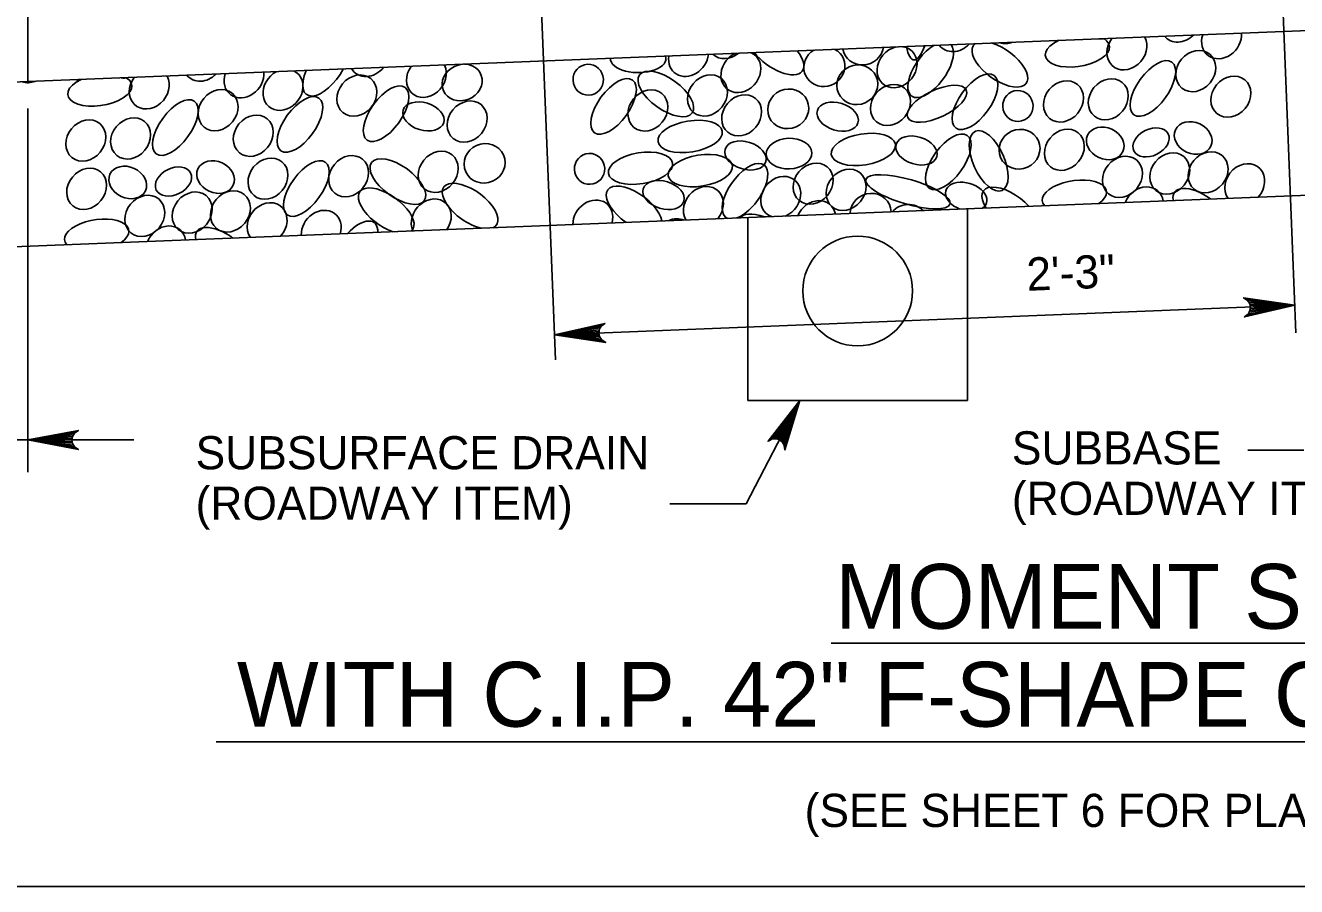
# Model space of a CAD drawing. Extents: x 638167 to 640248, y 296544 to 298920.
# Drawn here: x 638288.4 to 638406.1, y 297747.5 to 297827.2 of the extents above; entities that cross this region are included whole.
import ezdxf

# ---------------------------------------------------------------- set-up
doc = ezdxf.new("R2010")
doc.units = 0
doc.layers.add('1', color=7, linetype='Continuous')

msp = doc.modelspace()

# ---------------------------------------------------------------- linework, layer by layer
at = {"layer": '1'}
for p, q in [((638288.65, 297857.77), (638288.65, 297822.04)), ((638288.65, 297822.04), (638633.99, 297835.85)), ((638404.73, 297832.07), (638406.06, 297798.78)), ((638336.23, 297828.65), (638337.52, 297796.27)), ((638273.64, 297821.44), (638288.65, 297822.04)), ((638274.25, 297806.21), (638634.6, 297820.62)), ((638288.65, 297785.85), (638288.65, 297819.54)), ((638375.65, 297810.27), (638375.65, 297792.49)), ((638355.32, 297809.45), (638355.32, 297792.49)), ((638337.43, 297798.58), (638405.96, 297801.32)), ((638355.16, 297782.92), (638360.15, 297792.49)), ((638355.32, 297792.49), (638375.65, 297792.49)), ((638263.78, 297788.85), (638298.47, 297788.85)), ((638401.63, 297787.89), (638406.82, 297787.89)), ((638348.11, 297782.92), (638355.16, 297782.92)), ((638363.04, 297770.03), (638490.62, 297770.03)), ((638306.09, 297760.88), (638547.86, 297760.88)), ((638205.78, 297747.48), (638991.78, 297747.48))]:
    msp.add_line(p, q, dxfattribs=at)
for points in [[(638405.96, 297801.32), (638401.3, 297800.25), (638401.48, 297800.38), (638401.65, 297800.51), (638401.74, 297800.68), (638401.82, 297800.84), (638401.85, 297801), (638401.87, 297801.15), (638401.83, 297801.31), (638401.8, 297801.47), (638401.7, 297801.62), (638401.6, 297801.77), (638401.41, 297801.89), (638401.23, 297802.01), (638405.96, 297801.32), (638401.41, 297801.89), (638401.6, 297801.77), (638405.96, 297801.32), (638401.7, 297801.62), (638401.8, 297801.47), (638405.96, 297801.32), (638401.83, 297801.31), (638401.87, 297801.15), (638405.96, 297801.32), (638401.85, 297801), (638401.82, 297800.84), (638405.96, 297801.32), (638401.74, 297800.68), (638401.65, 297800.51), (638405.96, 297801.32), (638401.48, 297800.38)], [(638337.43, 297798.58), (638342.09, 297799.64), (638341.92, 297799.51), (638341.74, 297799.38), (638341.65, 297799.22), (638341.57, 297799.06), (638341.55, 297798.9), (638341.52, 297798.74), (638341.56, 297798.58), (638341.59, 297798.43), (638341.69, 297798.27), (638341.79, 297798.12), (638341.98, 297798), (638342.16, 297797.88), (638337.43, 297798.58), (638341.98, 297798), (638341.79, 297798.12), (638337.43, 297798.58), (638341.69, 297798.27), (638341.59, 297798.43), (638337.43, 297798.58), (638341.56, 297798.58), (638341.52, 297798.74), (638337.43, 297798.58), (638341.55, 297798.9), (638341.57, 297799.06), (638337.43, 297798.58), (638341.65, 297799.22), (638341.74, 297799.38), (638337.43, 297798.58), (638341.92, 297799.51)], [(638360.15, 297792.49), (638358.75, 297787.92), (638358.73, 297788.13), (638358.7, 297788.35), (638358.6, 297788.51), (638358.51, 297788.66), (638358.38, 297788.76), (638358.25, 297788.86), (638358.1, 297788.91), (638357.95, 297788.96), (638357.77, 297788.95), (638357.58, 297788.94), (638357.39, 297788.83), (638357.19, 297788.73), (638360.15, 297792.49), (638357.39, 297788.83), (638357.58, 297788.94), (638360.15, 297792.49), (638357.77, 297788.95), (638357.95, 297788.96), (638360.15, 297792.49), (638358.1, 297788.91), (638358.25, 297788.86), (638360.15, 297792.49), (638358.38, 297788.76), (638358.51, 297788.66), (638360.15, 297792.49), (638358.6, 297788.51), (638358.7, 297788.35), (638360.15, 297792.49), (638358.73, 297788.13)], [(638288.65, 297788.85), (638293.34, 297789.73), (638293.16, 297789.61), (638292.98, 297789.48), (638292.89, 297789.32), (638292.79, 297789.17), (638292.77, 297789.01), (638292.74, 297788.85), (638292.77, 297788.69), (638292.79, 297788.54), (638292.89, 297788.38), (638292.98, 297788.22), (638293.16, 297788.1), (638293.34, 297787.97), (638288.65, 297788.85), (638293.16, 297788.1), (638292.98, 297788.22), (638288.65, 297788.85), (638292.89, 297788.38), (638292.79, 297788.54), (638288.65, 297788.85), (638292.77, 297788.69), (638292.74, 297788.85), (638288.65, 297788.85), (638292.77, 297789.01), (638292.79, 297789.17), (638288.65, 297788.85), (638292.89, 297789.32), (638292.98, 297789.48), (638288.65, 297788.85), (638293.16, 297789.61)]]:
    msp.add_lwpolyline(points, dxfattribs=at)
msp.add_circle((638365.49, 297802.65), 5.08, dxfattribs=at)
for centre, major_axis, ratio, start_param, end_param in [((638390.42, 297825.04), (1.29, 1.57), 0.844245, 1.619643, 5.951196), ((638395.41, 297827.61), (1.29, 1.57), 0.844245, 2.967408, 4.603431), ((638399.19, 297826.07), (1.29, 1.57), 0.844245, 2.008108, 5.562731), ((638362.41, 297823.42), (-1.75, -0.78), 0.948581, 4.858014, 10.05193), ((638366, 297825.42), (-1.75, -0.78), 0.948581, 6.041055, 8.868889), ((638369.14, 297823.38), (1.29, 1.57), 0.844245, 0.812597, 6.758242), ((638372.25, 297823.14), (-1.76, -2.44), 0.479042, 3.984367, 9.301958), ((638371.14, 297828.08), (0.45, 4.03), 0.282192, 2.36721, 4.002176), ((638374.59, 297826.73), (1.29, 1.57), 0.844245, 2.937326, 4.633513), ((638378.66, 297823.64), (-2.44, 1.76), 0.479042, 6.144575, 11.609923), ((638379.47, 297827.47), (1.29, 1.57), 0.844245, 3.456732, 4.114107), ((638385.84, 297824.89), (-2.97, -0.48), 0.479042, 5.260141, 9.956857), ((638385.08, 297828.41), (-1.76, -2.44), 0.479042, 0.238343, 0.481611), ((638388.36, 297827.9), (1.29, 1.57), 0.844245, 3.627473, 3.943366), ((638345.17, 297824.17), (2.57, 0), 0.504072, 3.123827, 6.463685), ((638349.83, 297824.43), (1.29, 1.57), 0.844245, 2.187172, 5.383667), ((638353.45, 297826.08), (1.29, 1.57), 0.844245, 3.07937, 4.491469), ((638354.68, 297822.94), (1.29, 1.57), 0.844245, 1.061779, 6.50906), ((638357.93, 297824.79), (-2.44, 1.76), 0.479042, 1.014341, 4.173787), ((638299.9, 297821.42), (1.29, 1.57), 0.844245, 1.619643, 5.951196), ((638304.89, 297823.99), (1.29, 1.57), 0.844245, 2.967408, 4.603431), ((638308.67, 297822.45), (1.29, 1.57), 0.844245, 2.008108, 5.562731), ((638312.28, 297821.29), (1.29, 1.57), 0.844245, 1.11244, 6.458399), ((638316.22, 297823.29), (-1.76, -2.44), 0.479042, 5.130486, 8.155839), ((638320.25, 297824.42), (1.29, 1.57), 0.844245, 2.840874, 4.729965), ((638325.56, 297822.49), (1.29, 1.57), 0.844245, 1.646659, 5.92418), ((638328.87, 297821.96), (-1.73, -0.77), 0.87402, 4.347672, 10.501851), ((638288.95, 297823.85), (1.29, 1.57), 0.844245, 3.456732, 4.114107), ((638295.32, 297821.27), (-2.97, -0.48), 0.479042, 5.260141, 9.956857), ((638294.56, 297824.78), (-1.76, -2.44), 0.479042, 0.238343, 0.481611), ((638297.83, 297824.28), (1.29, 1.57), 0.844245, 3.627473, 3.943366), ((638355.06, 297811.89), (-1.76, -2.44), 0.479042, 0.613344, 6.389796), ((638401.33, 297812.53), (1.29, 1.57), 0.844245, 4.644979, 9.209045), ((638358.37, 297811.35), (1.29, 1.57), 0.844245, 4.147339, 9.706685), ((638321.84, 297810.08), (-2.44, 1.76), 0.479042, 3.037298, 8.434015), ((638329.61, 297810.52), (-2.44, 1.76), 0.479042, 2.873239, 8.598074), ((638344.78, 297810.25), (-2.44, 1.76), 0.479042, 3.57213, 7.899183), ((638351.21, 297810.42), (1.29, 1.57), 0.844245, 4.720434, 9.133591), ((638375.54, 297811.38), (1.88, -0.58), 0.646802, 5.825434, 10.881517), ((638379.57, 297810.16), (-2.44, 1.76), 0.479042, 4.285286, 7.186027), ((638385.56, 297811.43), (-2.97, -0.48), 0.479042, 2.351329, 6.582484), ((638391.96, 297810.38), (1.29, 1.57), 0.844245, 5.644884, 8.209141), ((638397.27, 297810.04), (-2.44, 1.76), 0.479042, 4.69169, 6.779622), ((638310.81, 297808.91), (1.29, 1.57), 0.844245, 4.644979, 9.209045), ((638326.01, 297809.26), (1.29, 1.57), 0.844245, 4.815265, 9.038759), ((638340.97, 297809.16), (1.29, 1.57), 0.844245, 5.210279, 8.643745), ((638361.62, 297809.11), (1.29, 1.57), 0.844245, 5.676034, 8.17799), ((638366.69, 297809.86), (-1.75, -0.78), 0.948581, 2.768835, 5.857924), ((638315.82, 297808.21), (1.29, 1.57), 0.844245, 5.179508, 8.674516), ((638358.37, 297807.7), (3.63, -1.8), 0.282192, 2.12602, 3.204967), ((638370.12, 297808.83), (-1.75, -0.78), 0.948581, 3.464469, 5.16229), ((638295.03, 297807.81), (-2.97, -0.48), 0.479042, 2.351329, 6.582484), ((638301.43, 297806.76), (1.29, 1.57), 0.844245, 5.644884, 8.209141), ((638306.75, 297806.42), (-2.44, 1.76), 0.479042, 4.69169, 6.779622), ((638318.95, 297806.55), (-1.76, -2.44), 0.479042, 2.538262, 4.464878), ((638348.48, 297807.43), (1.29, 1.57), 0.844245, 0.243434, 1.04422)]:
    msp.add_ellipse(centre, major_axis=major_axis, ratio=ratio, start_param=start_param, end_param=end_param, dxfattribs=at)
for centre, major_axis, ratio in [((638396.8, 297823.02), (1.29, 1.57), 0.844245), ((638365.46, 297821.75), (-1.75, -0.78), 0.948581), ((638392.83, 297821.41), (-1.76, -2.44), 0.479042), ((638319.12, 297820.75), (1.29, 1.57), 0.844245), ((638340.54, 297822.22), (-0.06, 1.43), 0.982495), ((638342.89, 297819.75), (-1.76, -2.44), 0.479042), ((638347.73, 297820.9), (-2.44, 1.76), 0.479042), ((638351.58, 297820.76), (1.29, 1.57), 0.844245), ((638376.36, 297820.18), (-1.76, -2.44), 0.479042), ((638388.7, 297820.4), (1.29, 1.57), 0.844245), ((638400.05, 297820.65), (1.29, 1.57), 0.844245), ((638306.27, 297819.4), (1.29, 1.57), 0.844245), ((638321.83, 297819.07), (-1.76, -2.44), 0.479042), ((638346.07, 297819.37), (1.29, 1.57), 0.844245), ((638359.06, 297819.52), (-1.75, -0.78), 0.948581), ((638368.53, 297819.88), (1.29, 1.57), 0.844245), ((638372.84, 297819.99), (2.71, 1.28), 0.422273), ((638384.55, 297820.21), (1.29, 1.57), 0.844245), ((638302.31, 297817.79), (-1.76, -2.44), 0.479042), ((638313.85, 297818.08), (-1.76, -2.44), 0.479042), ((638325.28, 297818.82), (1.88, -0.58), 0.646802), ((638329.33, 297818.34), (1.29, 1.57), 0.844245), ((638354.75, 297818.92), (1.29, 1.57), 0.844245), ((638363.64, 297818.8), (1.88, -0.58), 0.646802), ((638380.33, 297819.79), (-0.06, 1.43), 0.982495), ((638309.53, 297817.03), (1.29, 1.57), 0.844245), ((638294.02, 297816.59), (1.29, 1.57), 0.844245), ((638298.17, 297816.78), (1.29, 1.57), 0.844245), ((638349.98, 297816.96), (-2.97, -0.48), 0.479042), ((638380.48, 297815.78), (-1.75, -0.78), 0.948581), ((638384.63, 297815.73), (1.29, 1.57), 0.844245), ((638388.42, 297816.32), (1.64, -0.76), 0.796199), ((638392.66, 297816.41), (1.59, 0.79), 0.687276), ((638396.56, 297816.82), (1.64, -0.76), 0.796199), ((638355.1, 297815.2), (1.88, -0.58), 0.646802), ((638359.13, 297815.38), (2.11, 0.08), 0.671766), ((638366.02, 297815.76), (-2.97, -0.48), 0.479042), ((638370.94, 297815.66), (1.88, -0.58), 0.646802), ((638373.88, 297814.61), (-1.76, -2.44), 0.479042), ((638377.63, 297814.7), (1.23, -2.74), 0.479042), ((638326.65, 297813.69), (1.29, 1.57), 0.844245), ((638330.95, 297814.47), (-1.75, -0.78), 0.948581), ((638345.39, 297814.02), (-2.97, -0.48), 0.479042), ((638350.93, 297813.8), (-2.97, -0.48), 0.479042), ((638394.39, 297813.53), (1.29, 1.57), 0.844245), ((638397.94, 297813.64), (1.29, 1.57), 0.844245), ((638297.9, 297812.7), (1.64, -0.76), 0.796199), ((638302.14, 297812.79), (1.59, 0.79), 0.687276), ((638306.04, 297813.2), (1.64, -0.76), 0.796199), ((638310.89, 297813.05), (1.29, 1.57), 0.844245), ((638314.44, 297812.14), (-1.76, -2.44), 0.479042), ((638318.36, 297813.28), (1.29, 1.57), 0.844245), ((638322.92, 297812.78), (-2.44, 1.76), 0.479042), ((638340.67, 297813.96), (-0.06, 1.43), 0.982495), ((638361.37, 297812.59), (1.29, 1.57), 0.844245), ((638390.01, 297813.22), (1.29, 1.57), 0.844245), ((638294.1, 297812.11), (1.29, 1.57), 0.844245), ((638364.42, 297812.02), (1.29, 1.57), 0.844245), ((638370.15, 297811.84), (3.89, -1.14), 0.282192), ((638303.87, 297809.91), (1.29, 1.57), 0.844245), ((638307.41, 297810.02), (1.29, 1.57), 0.844245), ((638347.52, 297811.54), (1.88, -0.58), 0.646802), ((638299.48, 297809.6), (1.29, 1.57), 0.844245)]:
    msp.add_ellipse(centre, major_axis=major_axis, ratio=ratio, dxfattribs=at)

# ---------------------------------------------------------------- texts
for s, rotation, p in [('2\'-3"', 2.2906, (638381.19, 297802.66)), ('SUBBASE', 360, (638379.77, 297786.58)), ('SUBSURFACE DRAIN', 360, (638304.19, 297786.13)), ('(ROADWAY ITEM)', 360, (638379.77, 297781.91)), ('(ROADWAY ITEM)', 360, (638304.19, 297781.45))]:
    msp.add_text(s, height=3.072, rotation=rotation, dxfattribs=at).set_placement(p)
for s, height, p in [('MOMENT SLAB (AT-GRADE)', 6, (638363.4, 297771.36)), ('WITH C.I.P. 42" F-SHAPE CONCRETE BARRIER', 6, (638308.01, 297762.29)), ('(SEE SHEET 6 FOR PLAN OF C.I.P. MOMENT SLAB)', 3.072, (638360.58, 297753))]:
    msp.add_text(s, height=height, dxfattribs=at).set_placement(p)

doc.saveas('drawing.dxf')
